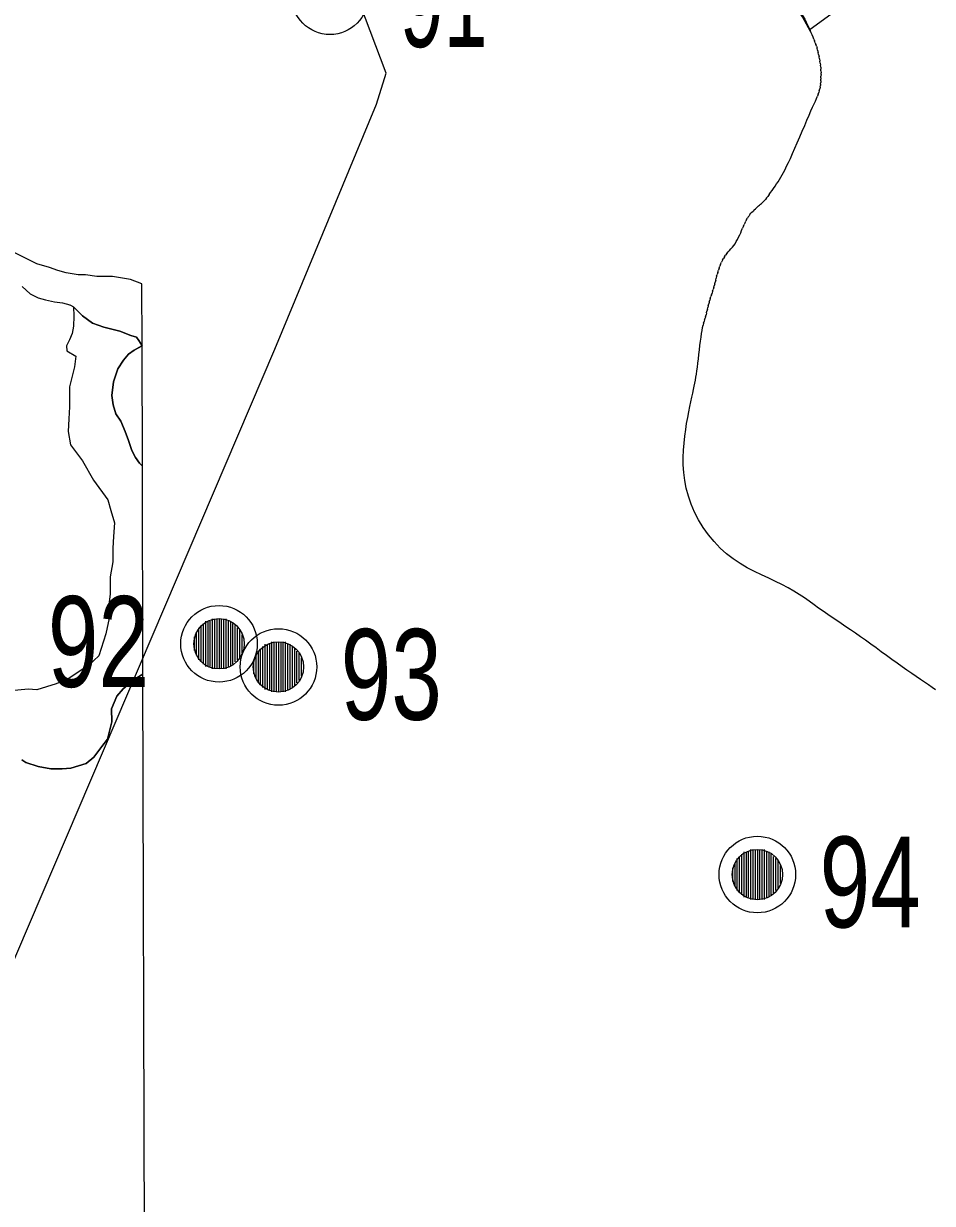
# Model space of a CAD drawing. Extents: x 553962 to 842807, y 8883888 to 9032388.
# Drawn here: x 691702 to 695707, y 8956482 to 8961682 of the extents above; entities that cross this region are included whole.
import ezdxf

# ---------------------------------------------------------------- set-up
doc = ezdxf.new("R2010")
doc.units = 0
doc.header["$LTSCALE"] = 160
for name, color, linetype, lineweight in [('15', 7, 'Continuous', 25), ('21', 7, 'Continuous', 25), ('27', 7, 'Continuous', 90), ('32', 7, 'Continuous', 13), ('33', 7, 'Continuous', 13), ('4', 7, 'Continuous', 13)]:
    doc.layers.add(name, color=color, linetype=linetype, lineweight=lineweight)

msp = doc.modelspace()

# ---------------------------------------------------------------- linework, layer by layer
at = {"layer": '15'}
msp.add_lwpolyline([(691240.8, 8956578.2), (692809.2, 8960246.9), (693257.6, 8961326.5), (693299.9, 8961463.3), (692951.1, 8962385.1), (692776, 8962756.9), (692786.9, 8963010.2)], dxfattribs=at)
at = {"layer": '21'}
for p, q in [((695185.1, 8961613.6), (695188.4, 8961605.4)), ((695191.4, 8961597.4), (695188.4, 8961605.4)), ((695191.4, 8961597.4), (695194.2, 8961589.4)), ((695196.8, 8961581.3), (695194.2, 8961589.4)), ((695196.8, 8961581.3), (695199.3, 8961572.8)), ((695201.7, 8961563.9), (695199.3, 8961572.8)), ((695201.7, 8961563.9), (695204, 8961554.7)), ((695206.1, 8961545.2), (695204, 8961554.7)), ((695206.1, 8961545.2), (695208.1, 8961535.5)), ((695210, 8961525.8), (695208.1, 8961535.5)), ((695210, 8961525.8), (695211.6, 8961516.2)), ((695213.1, 8961506.8), (695211.6, 8961516.2)), ((695213.1, 8961506.8), (695214.2, 8961497.7)), ((695215.1, 8961489), (695214.2, 8961497.7)), ((695215.1, 8961489), (695215.8, 8961480.6)), ((695216.2, 8961472.6), (695215.8, 8961480.6)), ((695216.2, 8961472.6), (695216.5, 8961464.9)), ((695216.5, 8961457.4), (695216.4, 8961450.1)), ((695216.5, 8961457.4), (695216.5, 8961464.9)), ((695212.3, 8961401), (695213.5, 8961408.2)), ((695214.3, 8961415.2), (695213.5, 8961408.2)), ((695214.3, 8961415.2), (695215, 8961422.2)), ((695215.5, 8961429.1), (695215, 8961422.2)), ((695215.5, 8961429.1), (695215.9, 8961436)), ((695216.2, 8961443), (695215.9, 8961436)), ((695216.2, 8961443), (695216.4, 8961450.1)), ((695203.7, 8961369.9), (695200.3, 8961361)), ((695203.7, 8961369.9), (695206.5, 8961378.2)), ((695208.8, 8961386.1), (695206.5, 8961378.2)), ((695208.8, 8961386.1), (695210.8, 8961393.7)), ((695212.3, 8961401), (695210.8, 8961393.7)), ((694950, 8960885.1), (694945.8, 8960881.5)), ((694950, 8960885.1), (694954.1, 8960888.7)), ((694958.2, 8960892.6), (694954.1, 8960888.7)), ((694958.2, 8960892.6), (694962.4, 8960896.8)), ((694966.8, 8960901.5), (694962.4, 8960896.8)), ((694966.8, 8960901.5), (694971.5, 8960906.9)), ((694976.7, 8960913), (694971.5, 8960906.9)), ((694976.7, 8960913), (694982.2, 8960920.1)), ((694988.2, 8960928.1), (694982.2, 8960920.1)), ((694895.4, 8960829.4), (694899.2, 8960834.8)), ((694903.2, 8960840.2), (694899.2, 8960834.8)), ((694903.2, 8960840.2), (694907.6, 8960845.4)), ((694912.2, 8960850.5), (694907.6, 8960845.4)), ((694912.2, 8960850.5), (694917.1, 8960855.5)), ((694922.1, 8960860.3), (694917.1, 8960855.5)), ((694922.1, 8960860.3), (694927, 8960865)), ((694932, 8960869.5), (694927, 8960865)), ((694932, 8960869.5), (694936.8, 8960873.7)), ((694941.4, 8960877.7), (694936.8, 8960873.7)), ((694941.4, 8960877.7), (694945.8, 8960881.5)), ((694874.5, 8960788.4), (694870.7, 8960779.5)), ((694874.5, 8960788.4), (694878.1, 8960796.7)), ((694881.6, 8960804.2), (694878.1, 8960796.7)), ((694881.6, 8960804.2), (694885, 8960811.2)), ((694888.3, 8960817.6), (694885, 8960811.2)), ((694888.3, 8960817.6), (694891.8, 8960823.7)), ((694895.4, 8960829.4), (694891.8, 8960823.7)), ((694813.6, 8960681.6), (694807.6, 8960674.9)), ((694813.6, 8960681.6), (694819.7, 8960688.5)), ((694825.8, 8960695.7), (694819.7, 8960688.5)), ((694773.6, 8960621), (694777.4, 8960629.7)), ((694781.6, 8960638.2), (694777.4, 8960629.7)), ((694781.6, 8960638.2), (694786, 8960646.3)), ((694790.9, 8960654), (694786, 8960646.3)), ((694790.9, 8960654), (694796.2, 8960661.2)), ((694801.8, 8960668.2), (694796.2, 8960661.2)), ((694801.8, 8960668.2), (694807.6, 8960674.9)), ((694756.5, 8960567.7), (694758.9, 8960576.3)), ((694761.3, 8960585.2), (694758.9, 8960576.3)), ((694761.3, 8960585.2), (694764, 8960594.1)), ((694767, 8960603.1), (694764, 8960594.1)), ((694767, 8960603.1), (694770.2, 8960612.1)), ((694773.6, 8960621), (694770.2, 8960612.1)), ((694743.7, 8960517.7), (694745.9, 8960525.8)), ((694748.1, 8960534), (694745.9, 8960525.8)), ((694748.1, 8960534), (694750.2, 8960542.3)), ((694752.2, 8960550.6), (694750.2, 8960542.3)), ((694752.2, 8960550.6), (694754.3, 8960559.1)), ((694756.5, 8960567.7), (694754.3, 8960559.1)), ((694728.6, 8960470), (694726.2, 8960462.1)), ((694728.6, 8960470), (694731.2, 8960478)), ((694733.8, 8960485.9), (694731.2, 8960478)), ((694733.8, 8960485.9), (694736.3, 8960493.8)), ((694738.8, 8960501.8), (694736.3, 8960493.8)), ((694738.8, 8960501.8), (694741.3, 8960509.7)), ((694743.7, 8960517.7), (694741.3, 8960509.7)), ((694715.5, 8960421.7), (694713.5, 8960413.8)), ((694715.5, 8960421.7), (694717.4, 8960429.8)), ((694719.5, 8960437.8), (694717.4, 8960429.8)), ((694719.5, 8960437.8), (694721.6, 8960446)), ((694723.8, 8960454.1), (694721.6, 8960446)), ((694723.8, 8960454.1), (694726.2, 8960462.1)), ((694699.2, 8960361.1), (694701.4, 8960369.2)), ((694703.5, 8960376.8), (694701.4, 8960369.2)), ((694703.5, 8960376.8), (694705.6, 8960383.9)), ((694707.7, 8960391.1), (694705.6, 8960383.9)), ((694707.7, 8960391.1), (694709.7, 8960398.4)), ((694711.6, 8960406), (694709.7, 8960398.4)), ((694711.6, 8960406), (694713.5, 8960413.8)), ((694699.2, 8960361.1), (694696.9, 8960351.9))]:
    msp.add_line(p, q, dxfattribs=at)
for points in [[(695116.9, 8961748), (695124.2, 8961736.8), (695131.2, 8961725.1), (695138.1, 8961712.9), (695144.8, 8961700.5), (695151.1, 8961688), (695157.2, 8961675.6), (695162.9, 8961663.6), (695168.2, 8961652.1)], [(695169, 8961656.4), (695276, 8961734.9)], [(695185.1, 8961613.6), (695181.5, 8961622.3), (695177.5, 8961631.4), (695173.1, 8961641.4), (695168.2, 8961652.1)], [(694988.2, 8960928.1), (694994.5, 8960936.7), (695001, 8960945.8), (695007.6, 8960955.3), (695014.2, 8960965), (695020.7, 8960974.9), (695027, 8960984.7), (695033.1, 8960994.3), (695039.1, 8961004.1), (695045.1, 8961014.5), (695051.4, 8961025.8), (695057.9, 8961038.3), (695065, 8961052.5), (695072.8, 8961068.8), (695081.4, 8961087.4), (695091, 8961108.7), (695101.2, 8961132), (695112, 8961156.7), (695123, 8961182.2), (695134, 8961207.7), (695144.6, 8961232.5), (695154.7, 8961256.1), (695164, 8961277.6), (695172.3, 8961296.5), (695179.6, 8961313), (695186, 8961327.5), (695191.5, 8961340.1), (695196.2, 8961351.1), (695200.3, 8961361)], [(694825.8, 8960695.7), (694831.7, 8960703.3), (694837.5, 8960711.5), (694843, 8960720.4), (694848.2, 8960730), (694853.2, 8960739.8), (694858, 8960749.9), (694862.5, 8960760), (694866.7, 8960769.9), (694870.7, 8960779.5)], [(694610.5, 8959801.8), (694612.9, 8959833), (694616.2, 8959863.1), (694620.1, 8959891.9), (694624.3, 8959919.5), (694628.9, 8959945.6), (694633.6, 8959970.2), (694638.3, 8959993.2), (694642.9, 8960014.6), (694647.3, 8960034.3), (694651.3, 8960052.2), (694654.8, 8960068.3), (694657.9, 8960082.9), (694660.6, 8960096.7), (694663.1, 8960109.9), (694665.3, 8960123.1), (694667.5, 8960136.7), (694669.5, 8960151.2), (694671.6, 8960167.1), (694673.7, 8960184.6), (694675.9, 8960203.4), (694678.2, 8960223), (694680.5, 8960243), (694682.8, 8960262.7), (694685.2, 8960281.7), (694687.6, 8960299.4), (694689.9, 8960315.5), (694692.3, 8960329.4), (694694.6, 8960341.5), (694696.9, 8960351.9)], [(695412.6, 8958963.5), (695390.1, 8958979.4), (695368.3, 8958994.5), (695347.1, 8959009), (695326.3, 8959023.1), (695305.9, 8959036.8), (695285.8, 8959050.4), (695265.9, 8959063.9), (695246.1, 8959077.5), (695226.2, 8959091.4), (695206.1, 8959105.7), (695185.8, 8959120.3), (695164.8, 8959135.2), (695143.1, 8959150.1), (695120.4, 8959165), (695096.6, 8959179.9), (695071.3, 8959194.5), (695044.4, 8959208.8), (695015.8, 8959222.9), (694985.9, 8959236.9), (694954.9, 8959251.4), (694923.4, 8959266.7), (694891.7, 8959283.3), (694860.2, 8959301.5), (694829.4, 8959321.8), (694799.7, 8959344.6), (694771.4, 8959370.2), (694744.8, 8959398.3), (694720.1, 8959428.6), (694697.5, 8959460.6), (694677.2, 8959494), (694659.3, 8959528.4), (694644.1, 8959563.4), (694631.8, 8959598.6), (694622.4, 8959633.7), (694615.8, 8959668.4), (694611.6, 8959702.8), (694609.5, 8959736.5), (694609.3, 8959769.6), (694610.5, 8959801.8)], [(695721.7, 8958745.6), (695706.5, 8958756), (695690.3, 8958767), (695673.1, 8958778.7), (695655, 8958791), (695636, 8958803.9), (695616.2, 8958817.6), (695595.5, 8958832), (695574, 8958847.1), (695551.8, 8958862.9), (695529, 8958879.4), (695505.8, 8958896.2), (695482.3, 8958913.2), (695458.9, 8958930.2), (695435.6, 8958947.1), (695412.6, 8958963.5)]]:
    msp.add_lwpolyline(points, dxfattribs=at)
msp.add_spline([(695170.7, 8961646.8), (695094.7, 8961773.3), (694929.1, 8961938.8), (694680.8, 8962114.8), (694540.3, 8962171.7), (694427.3, 8962232.6), (694366.5, 8962247.8), (694270.9, 8962269.5), (694127.6, 8962297.8), (693938.6, 8962389.1), (693764.8, 8962478.2), (693575.8, 8962545.5), (693330.4, 8962615.1), (693210.9, 8962636.8), (692989.3, 8962745.5), (692906.8, 8962786.8), (692817.7, 8962838.9), (692765.6, 8962886.7), (692691.7, 8962969.3), (692639.6, 8963030.2), (692544, 8963141), (692498.4, 8963178), (692402.8, 8963258.4), (692300.7, 8963319.2), (692140, 8963421.4), (691977.1, 8963493.1), (691866.3, 8963514.8), (691638.2, 8963532.2), (691462.3, 8963549.6), (691336.3, 8963562.6), (691273.3, 8963588.7), (691203.8, 8963640.9), (691103.8, 8963762.6), (691048.1, 8963842.5), (691024.9, 8963935.4), (691027.8, 8964068.8), (691022, 8964216.8), (690966.8, 8964338.7), (690920.4, 8964422.8), (690914.6, 8964530.2), (690952.3, 8964623), (691022, 8964721.7), (691088.7, 8964808.7), (691297.6, 8965101.8), (691483.3, 8965383.2), (691582, 8965539.9), (691761.8, 8965929.2), (692017.2, 8966518.5), (692139.1, 8966942.3), (692231.9, 8967543.3), (692246.4, 8967740.7), (692124.5, 8967943.9), (691973.7, 8968039.7), (691700.9, 8968077.4), (691448.5, 8968103.5)], degree=3, dxfattribs=at)
at = {"layer": '27'}
for points in [[(637260.6, 8972975.8), (641524.5, 8971056.2), (652526.1, 8965412.7), (653164.3, 8965062.8), (670790.5, 8953770.1), (686194, 8943929.9), (696283.3, 8937647.1)], [(694874, 8947402.7), (694491.4, 8947729), (693981.6, 8948105.1), (692654.2, 8949437.3), (691811.8, 8950292), (691552.9, 8951277.6), (691093.4, 8951755.3), (689976, 8951721.8), (689441.2, 8951996.3), (689158.9, 8952576.6), (688699.5, 8953029), (687605.5, 8953400.8), (685873.4, 8954400.8), (684752.3, 8955101.5), (681638, 8958243.7), (680641.1, 8959527.7), (679425.4, 8960995.9)]]:
    msp.add_spline(points, degree=3, dxfattribs=at)
at = {"layer": '32'}
msp.add_circle((693052, 8961802), 168.7, dxfattribs=at)
at = {"layer": '33'}
for p, q in [((692473, 8959018), (692473, 8958878)), ((692483, 8959028), (692483, 8958868)), ((692493, 8959038), (692493, 8958858)), ((692503, 8959048), (692503, 8958848)), ((692513, 8959048), (692513, 8958848)), ((692523, 8959048), (692523, 8958848)), ((692533, 8959058), (692533, 8958838)), ((692543, 8959058), (692543, 8958838)), ((692553, 8959058), (692553, 8958838)), ((692563, 8959058), (692563, 8958838)), ((692573, 8959058), (692573, 8958838)), ((692583, 8959058), (692583, 8958838)), ((692593, 8959058), (692593, 8958838)), ((692603, 8959048), (692603, 8958848)), ((692613, 8959048), (692613, 8958848)), ((692623, 8959038), (692623, 8958858)), ((692633, 8959028), (692633, 8958868)), ((692643, 8959018), (692643, 8958878)), ((692453, 8958978), (692453, 8958918)), ((692463, 8958998), (692463, 8958898)), ((692653, 8959008), (692653, 8958888)), ((692663, 8958988), (692663, 8958908)), ((692735, 8958916), (692735, 8958776)), ((692745, 8958926), (692745, 8958766)), ((692755, 8958936), (692755, 8958756)), ((692765, 8958946), (692765, 8958746)), ((692775, 8958946), (692775, 8958746)), ((692785, 8958946), (692785, 8958746)), ((692795, 8958956), (692795, 8958736)), ((692805, 8958956), (692805, 8958736)), ((692815, 8958956), (692815, 8958736)), ((692825, 8958956), (692825, 8958736)), ((692835, 8958956), (692835, 8958736)), ((692845, 8958956), (692845, 8958736)), ((692855, 8958956), (692855, 8958736)), ((692865, 8958946), (692865, 8958746)), ((692875, 8958946), (692875, 8958746)), ((692885, 8958936), (692885, 8958756)), ((692895, 8958926), (692895, 8958766)), ((692905, 8958916), (692905, 8958776)), ((692715, 8958876), (692715, 8958816)), ((692725, 8958896), (692725, 8958796)), ((692915, 8958906), (692915, 8958786)), ((692925, 8958886), (692925, 8958806)), ((694876, 8958031), (694876, 8957831)), ((694886, 8958031), (694886, 8957831)), ((694896, 8958031), (694896, 8957831)), ((694906, 8958041), (694906, 8957821)), ((694916, 8958041), (694916, 8957821)), ((694926, 8958041), (694926, 8957821)), ((694936, 8958041), (694936, 8957821)), ((694946, 8958041), (694946, 8957821)), ((694956, 8958041), (694956, 8957821)), ((694966, 8958041), (694966, 8957821)), ((694976, 8958031), (694976, 8957831)), ((694986, 8958031), (694986, 8957831)), ((694836, 8957981), (694836, 8957881)), ((694846, 8958001), (694846, 8957861)), ((694856, 8958011), (694856, 8957851)), ((694866, 8958021), (694866, 8957841)), ((694996, 8958021), (694996, 8957841)), ((695006, 8958011), (695006, 8957851)), ((695016, 8958001), (695016, 8957861)), ((695026, 8957991), (695026, 8957871)), ((694826, 8957961), (694826, 8957901)), ((695036, 8957971), (695036, 8957891))]:
    msp.add_line(p, q, dxfattribs=at)
for centre, radius in [((692563, 8958948), 168.7), ((692563, 8958948), 111), ((692825, 8958846), 168.7), ((692825, 8958846), 111), ((694936, 8957931), 168.7), ((694936, 8957931), 111)]:
    msp.add_circle(centre, radius, dxfattribs=at)
at = {"layer": '4'}
for points in [[(691695.6, 8960523.5), (691731.2, 8960489.8), (691765.6, 8960472.6), (691797.5, 8960463.6), (691837.8, 8960455), (691873, 8960451.1), (691905.8, 8960441.7), (691922.2, 8960432.8), (691961.4, 8960394.2), (691983.2, 8960377.9), (692006, 8960361.6), (692055, 8960344.2), (692125.8, 8960325.7), (692174.8, 8960307.2), (692199.9, 8960299.5), (692209.7, 8960284.3), (692223.7, 8960261.4), (692222.9, 8960534.9), (692173.3, 8960553.7), (692093.8, 8960566.7), (692024.3, 8960566.7), (691974.8, 8960573.7), (691941.8, 8960573.7), (691888.8, 8960583.7), (691852.8, 8960593.2), (691816.3, 8960606.7), (691759.8, 8960623.2), (691634.3, 8960685.7)], [(691695.6, 8960523.5), (691731.2, 8960489.8), (691765.6, 8960472.6), (691797.5, 8960463.6), (691837.8, 8960455), (691873, 8960451.1), (691895.3, 8960444.7), (691909, 8960440), (691922.2, 8960432.8), (691923.5, 8960391.8), (691922, 8960347.5), (691915.8, 8960316), (691904.6, 8960287.2), (691891, 8960261.1), (691892.8, 8960239.4), (691931.3, 8960215.2), (691925.6, 8960168.5), (691904.5, 8960080.7), (691904.5, 8960035), (691904.5, 8959992.9), (691901, 8959940.2), (691897.5, 8959884), (691908, 8959824.2), (691960.8, 8959754), (692010, 8959669.7), (692073.3, 8959581.8), (692085.7, 8959535.2), (692102, 8959481.5), (692097.4, 8959420.8), (692095, 8959369.5), (692095, 8959308.8), (692083.3, 8959243.4), (692083.3, 8959166.4), (692076.3, 8959110.4), (692078.7, 8959061.3), (692064.7, 8958991.3), (692033.2, 8958894.8), (691988.6, 8958853.2), (691897.7, 8958794.3), (691844.9, 8958772), (691760.2, 8958744.6), (691722.3, 8958748.4), (691644.7, 8958741)], [(692117.1, 8960160.5), (692142.5, 8960197.6), (692163.8, 8960224.8), (692188.5, 8960241.7), (692223.6, 8960261.6), (692209.7, 8960284.3), (692199.9, 8960299.5), (692174.8, 8960307.2), (692125.8, 8960325.7), (692055, 8960344.2), (692006, 8960361.6), (691983.2, 8960377.9), (691961.4, 8960394.2), (691922.2, 8960432.8), (691923.5, 8960391.8), (691922, 8960347.5), (691915.8, 8960316), (691904.6, 8960287.2), (691891, 8960261.1), (691892.8, 8960239.4), (691931.3, 8960215.2), (691925.6, 8960168.5), (691904.5, 8960080.7), (691904.5, 8960035), (691904.5, 8959992.9), (691901, 8959940.2), (691897.5, 8959884), (691908, 8959824.2), (691960.8, 8959754), (692010, 8959669.7), (692073.3, 8959581.8), (692085.7, 8959535.2), (692102, 8959481.5), (692097.4, 8959420.8), (692095, 8959369.5), (692095, 8959308.8), (692083.3, 8959243.4), (692083.3, 8959166.4), (692076.3, 8959110.4), (692078.7, 8959061.3), (692064.7, 8958991.3), (692033.2, 8958894.8), (691988.6, 8958853.2), (691897.7, 8958794.3), (691844.9, 8958772), (691760.2, 8958744.6), (691722.3, 8958748.4), (691644.7, 8958741)], [(691694.4, 8958436.9), (691710.9, 8958425.3), (691766.1, 8958406.9), (691821.6, 8958397.3), (691872.3, 8958396.8), (691909.2, 8958400.6), (691978, 8958420.2), (692010.7, 8958448.2), (692045.8, 8958494.9), (692071.5, 8958527.6), (692090.2, 8958604.6), (692088.4, 8958662), (692113.2, 8958716.9), (692141, 8958748.9), (692193.3, 8958794), (692227.9, 8958814), (692225.2, 8959730.8), (692212.8, 8959743.5), (692194.7, 8959769.6), (692179.3, 8959800.5), (692164.3, 8959844.2), (692149.2, 8959884.1), (692130.5, 8959929.1), (692108.8, 8959961.6), (692096.3, 8960001.4), (692090.1, 8960042.2), (692098.6, 8960102.8), (692117.1, 8960160.5)], [(691681, 8956312.8), (691707.1, 8956334.8), (691720.1, 8956343.2), (691750.6, 8956345.9), (691792.5, 8956344.4), (691838.1, 8956342.8), (691869.7, 8956340.5), (691930.3, 8956333.2), (691981.8, 8956318.7), (692027.2, 8956309.5), (692060.9, 8956294.4), (692102.7, 8956291.7), (692130.6, 8956290.7), (692174, 8956298), (692210, 8956313.2), (692235.2, 8956328.8), (692227.9, 8958814)], [(692227.9, 8958814), (692193.3, 8958794), (692141, 8958748.9), (692113.2, 8958716.9), (692088.4, 8958662), (692090.2, 8958604.6), (692071.5, 8958527.6), (692045.8, 8958494.9), (692010.7, 8958448.2), (691978, 8958420.2), (691909.2, 8958400.6), (691872.3, 8958396.8), (691821.6, 8958397.3), (691766.1, 8958406.9), (691710.9, 8958425.3), (691694.4, 8958436.9)]]:
    msp.add_lwpolyline(points, dxfattribs=at)
msp.add_lwpolyline([(692223.7, 8960261.4), (692222.1, 8960260.8), (692188.5, 8960241.7), (692163.8, 8960224.8), (692142.5, 8960197.6), (692117.1, 8960160.5), (692098.6, 8960102.8), (692090.1, 8960042.2), (692096.3, 8960001.4), (692108.8, 8959961.6), (692130.5, 8959929.1), (692149.2, 8959884.1), (692164.3, 8959844.2), (692179.3, 8959800.5), (692194.7, 8959769.6), (692212.8, 8959743.5), (692225.2, 8959730.8)], close=True, dxfattribs=at)

# ---------------------------------------------------------------- texts
at = {"layer": '32', "width": 0.65}
msp.add_text('91', height=400, dxfattribs=at).set_placement((693359.8, 8961578.3))
at = {"layer": '33', "width": 0.75}
for s, p in [('92', (691808.5, 8958758)), ('93', (693099.2, 8958613.1)), ('94', (695210.2, 8957698.1))]:
    msp.add_text(s, height=400, dxfattribs=at).set_placement(p)

doc.saveas('drawing.dxf')
